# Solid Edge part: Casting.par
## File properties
Author: Deepak Maini
Template: Normal.par
Last saved by: Administrator
Revision: 9
Application: Solid Edge
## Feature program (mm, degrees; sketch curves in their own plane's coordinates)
sketch for "unnamed Protrusion 1" plane through (0, 0, 0) normal (0, -1, 0) x-axis (1, 0, 0)
  line (0, 0) -> (0, 0)
  line (-104, 0) -> (104, 0)
  line (104, 0) -> (100, 14)
  line (100, 14) -> (-100, 14)
  line (-100, 14) -> (-104, 0)
  dimension (linear) = 104
  dimension (linear) = 104
extrude "unnamed Protrusion 1" add finite 46 symmetric
sketch for "unnamed Protrusion 2" plane through (0, 0, 0) normal (0, 0, 1) x-axis (1, 0, 0)
  line (-48.8569, 23) -> (48.8569, 23)
  arc centre (0, 0) radius 54 from (48.8569, 23) to (48.8569, -23) cw
  line (-48.8569, -23) -> (48.8569, -23)
  arc centre (0, 0) radius 54 from (-48.8569, -23) to (-48.8569, 23) cw
extrude "unnamed Protrusion 2" add finite 68 along +normal
sketch for "unnamed Cutout 1" plane through (0, 0, 0) normal (0, -1, 0) x-axis (1, 0, 0)
  line (24, 52) -> (24, 48)
  line (28, 52) -> (24, 52)
  line (28, 68) -> (28, 52)
  line (-28, 68) -> (28, 68)
  line (-28, 52) -> (-28, 68)
  line (-24, 52) -> (-28, 52)
  line (-24, 48) -> (-24, 52)
  arc centre (0, 48) radius 24 from (24, 48) to (-24, 48) cw
extrude "unnamed Cutout 1" cut finite 46 symmetric
chamfer "unnamed Chamfer 1"
fillet "unnamed Round 1"
sketch for "unnamed Hole 1" plane through (-41, 0, 68) normal (0, 0, 1) x-axis (0, 1, 0)
  hole centre (0, -80) bore radius 6
hole "unnamed Hole 1" through
sketch for "unnamed Cutout 2" plane through (0, 0, 0) normal (0, 0, 1) x-axis (1, 0, 0)
  line (23.9671, 14) -> (23.9671, -14)
  line (23.9671, -14) -> (51.9671, -14)
  line (51.9671, -14) -> (51.9671, 14)
  line (51.9671, 14) -> (23.9671, 14)
extrude "unnamed Cutout 2" cut finite 12 along +normal
sketch for "unnamed Cutout 3" plane through (0, 0, 0) normal (0, 0, 1) x-axis (1, 0, 0)
  line (71, 6) -> (71, -6)
  line (71, -6) -> (91, -6)
  line (91, -6) -> (91, 6)
  line (91, 6) -> (71, 6)
extrude "unnamed Cutout 3" cut through along +normal
fillet "unnamed Round 2"
mirror "unnamed Mirror 1" of "unnamed Round 2", "unnamed Cutout 3", "unnamed Cutout 2", "unnamed Hole 1"
pattern "unnamed Pattern 1"
sketch for "unnamed Cutout 4" plane through (0, 0, 0) normal (0, 0, 1) x-axis (1, 0, 0)
  line (-97.5, 20) -> (-97.5, -20)
  line (-97.5, -20) -> (97.5, -20)
  line (97.5, -20) -> (97.5, 20)
  line (97.5, 20) -> (-97.5, 20)
extrude "unnamed Cutout 4" cut finite 2 along +normal
sketch for "unnamed Hole 2" plane through (-41, 0, 68) normal (0, 0, 1) x-axis (1, 0, 0)
  hole centre (41, 0) bore radius 4
hole "unnamed Hole 2" finite
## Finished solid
Body 1: solid body, 53 faces, 134 edges, 84 vertices.
  Faces by surface: plane 39, cylinder 10, cone 2, torus 2
  Edges by curve: line 106, circle 23, intersection 5
Bounding box of the edges (mm; curved faces can reach further): 208.000 x 46.000 x 68.000, from (-104, -23, 0) to (104, 23, 68).
Cylindrical faces by radius (mm): R4 x1, R6 x6, R24 x1, R54 x2
Conical faces (half-angle, radius in mm at the cone's reference point): 45 deg R24 x1, 45 deg R26 x1
Toroidal faces (ring radius, tube radius in mm): R62 r8 x2
Planar faces by outward normal: +x 5, +y 6, +z 7, -x 5, -y 6, -z 4, oblique 6
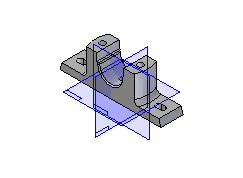
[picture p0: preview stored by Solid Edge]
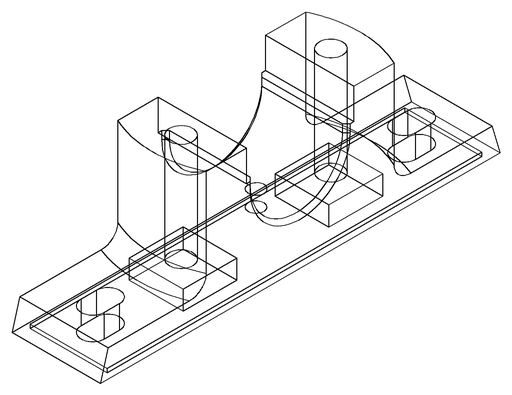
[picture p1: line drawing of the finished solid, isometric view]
